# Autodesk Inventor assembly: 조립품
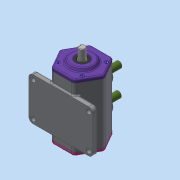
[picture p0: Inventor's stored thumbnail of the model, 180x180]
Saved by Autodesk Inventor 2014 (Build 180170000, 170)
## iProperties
Created: 2021-06
Part Number: 조립품
Document SubType Name: Assembly
Designer: net
Author: net
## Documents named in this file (11)
- C:\Users\net\Desktop\710606V1040\조립품.iam
- C:\Users\net\Desktop\710606V1040\본체.ipt
- C:\Users\net\Desktop\710606V1040\뒷커버.ipt
- C:\Users\net\Desktop\710606V1040\베어링 6203.ipt
- C:\Users\net\Desktop\710606V1040\베어링 6302.ipt
- C:\Users\net\Desktop\710606V1040\볼트 M4.ipt
- C:\Users\net\Desktop\710606V1040\부시.ipt
- C:\Users\net\Desktop\710606V1040\슬라이더.ipt
- C:\Users\net\Desktop\710606V1040\앞커버.ipt
- C:\Users\net\Desktop\710606V1040\오일실.ipt
- C:\Users\net\Desktop\710606V1040\편심축.ipt
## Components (10 placed, 3 different names)
1. 7-베어링 6203:1
2. 8-오일실:1
3. 9-M4-소켓머리:1
4. 9-M4-소켓머리:3
5. 9-M4-소켓머리:4
6. 9-M4-소켓머리:5
7. 9-M4-소켓머리:2
8. 9-M4-소켓머리:6
9. 9-M4-소켓머리:7
10. 9-M4-소켓머리:8
